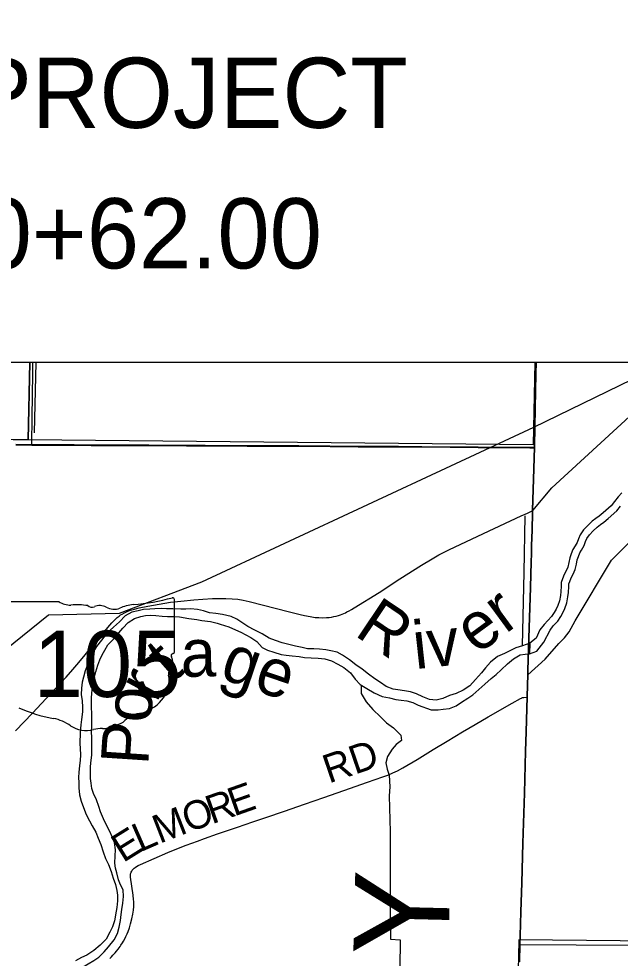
# Model space of a CAD drawing. Extents: x 0 to 34, y 0 to 22.
# Drawn here: x 6.448 to 7.646, y 14.995 to 16.867 of the extents above; entities that cross this region are included whole.
import ezdxf

# ---------------------------------------------------------------- set-up
doc = ezdxf.new("R2010")
doc.units = 0
for name, color, linetype in [('GM_X_City_Street', 7, 'Continuous'), ('GM_X_County_Road', 7, 'Continuous'), ('GM_X_County_Text', 7, 'Continuous'), ('GM_X_Major_River', 7, 'Continuous'), ('GM_X_Major_River_Text', 7, 'Continuous'), ('GM_X_Minor_River', 7, 'Continuous'), ('GM_X_Rail_Line', 7, 'Continuous'), ('GM_X_Section', 7, 'Continuous'), ('GM_X_State_Location', 7, 'Continuous'), ('GM_X_State_Route', 7, 'Continuous'), ('GM_X_State_Shield', 7, 'Continuous'), ('GM_X_Township_Road', 7, 'Continuous'), ('GM_X_Township_Road_Text', 7, 'Continuous'), ('GM_X_US_Route', 7, 'Continuous'), ('SH_Cut_Line', 7, 'Continuous'), ('SH_Text', 7, 'Continuous')]:
    doc.layers.add(name, color=color, linetype=linetype)

msp = doc.modelspace()

# ---------------------------------------------------------------- linework, layer by layer
at = {"layer": 'GM_X_City_Street'}
msp.add_lwpolyline([(7.4233, 14.1), (8.4275, 14.1), (8.4534, 15.0216), (7.4447, 15.0317), (7.4446, 15.029)], close=True, dxfattribs=at)
at = {"layer": 'GM_X_County_Road'}
msp.add_line((6.4425, 16.0181), (6.4745, 16.0177), dxfattribs=at)
for points in [[(6.4745, 16.0177), (6.5089, 16.0173), (6.5587, 16.0172), (6.5929, 16.017), (6.6302, 16.0168), (6.655, 16.0168), (6.7079, 16.0166), (6.7825, 16.0161), (6.8198, 16.0159), (6.9037, 16.0156), (7.0063, 16.0153), (7.0684, 16.0148), (7.1244, 16.0144), (7.2052, 16.0141), (7.2518, 16.0138), (7.3637, 16.0128), (7.4321, 16.0125), (7.4663, 16.0124), (7.4758, 16.0124)], [(7.4626, 15.5598), (7.4969, 15.5909), (7.5242, 15.6224), (7.5356, 15.6338), (7.5451, 15.6456), (7.5565, 15.6672), (7.6294, 15.7881), (7.7715, 15.9302)], [(7.447, 15.0225), (8.4514, 15.0162), (8.9, 15.0119)]]:
    msp.add_lwpolyline(points, dxfattribs=at)
at = {"layer": 'GM_X_Major_River'}
msp.add_line((7.4666, 15.6231), (7.4658, 15.6015), dxfattribs=at)
for points in [[(7.6498, 15.9222), (7.6426, 15.9146), (7.6354, 15.9051), (7.6282, 15.8963)], [(7.6282, 15.8963), (7.6123, 15.8829), (7.6044, 15.8761), (7.598, 15.8711), (7.5908, 15.8657), (7.5821, 15.8573), (7.5734, 15.8486), (7.567, 15.839), (7.5632, 15.831), (7.561, 15.8234), (7.5568, 15.8166), (7.5523, 15.8097), (7.5489, 15.8006), (7.5463, 15.793), (7.5444, 15.7839), (7.5422, 15.7744), (7.5388, 15.7668), (7.535, 15.7595), (7.5316, 15.7512), (7.529, 15.7439), (7.529, 15.7363), (7.5283, 15.7257), (7.5272, 15.7177), (7.5254, 15.7071), (7.5224, 15.698), (7.5186, 15.6907), (7.5148, 15.6839), (7.5099, 15.6763), (7.502, 15.6679), (7.4948, 15.6599), (7.4866, 15.6492), (7.4789, 15.6329), (7.4666, 15.6231)], [(7.64, 15.8867), (7.6473, 15.8957)], [(7.4658, 15.6015), (7.4802, 15.6069), (7.4942, 15.6249), (7.5067, 15.6485), (7.5131, 15.6576), (7.5219, 15.6669), (7.5279, 15.6761), (7.532, 15.6836), (7.5364, 15.6921), (7.5401, 15.7034), (7.5422, 15.7154), (7.5434, 15.7241), (7.5442, 15.7359), (7.5442, 15.7413), (7.5458, 15.7457), (7.5488, 15.7532), (7.5525, 15.7602), (7.5566, 15.7695), (7.5592, 15.7806), (7.5609, 15.789), (7.5632, 15.7955), (7.5659, 15.8028), (7.5696, 15.8085), (7.575, 15.8173), (7.5774, 15.8256), (7.5802, 15.8315), (7.5852, 15.8389), (7.5927, 15.8465), (7.6006, 15.8541), (7.6071, 15.859), (7.614, 15.8643), (7.6222, 15.8714), (7.64, 15.8867)], [(7.4666, 15.6231), (7.4517, 15.6179), (7.4383, 15.6133), (7.4264, 15.6079), (7.4161, 15.602), (7.4019, 15.5963), (7.3878, 15.5849), (7.3782, 15.5737), (7.3704, 15.5637), (7.3584, 15.5507), (7.3471, 15.5377), (7.3336, 15.5293), (7.3194, 15.5228), (7.3064, 15.5186), (7.2934, 15.5128), (7.2797, 15.509), (7.2669, 15.5108), (7.2534, 15.5157), (7.241, 15.5217), (7.2286, 15.5258), (7.2165, 15.5279), (7.2037, 15.5298), (7.1939, 15.5312), (7.18, 15.5368), (7.1689, 15.5447), (7.1577, 15.5521), (7.145, 15.5608), (7.1324, 15.5714), (7.1198, 15.58), (7.1071, 15.5894), (7.0933, 15.5989), (7.0829, 15.6048), (7.0701, 15.6078), (7.0599, 15.6095), (7.0478, 15.6106), (7.0365, 15.6113), (7.0236, 15.6116), (7.013, 15.6141), (6.9995, 15.6167), (6.9863, 15.6201), (6.9731, 15.6238), (6.96, 15.6283), (6.9472, 15.6328), (6.9331, 15.6415), (6.9189, 15.6486), (6.9046, 15.6562), (6.895, 15.6625), (6.8827, 15.6708), (6.8714, 15.676), (6.8545, 15.6798), (6.8409, 15.6817), (6.8284, 15.6831), (6.8164, 15.6872), (6.8046, 15.6901), (6.7908, 15.6912), (6.7809, 15.6907), (6.7711, 15.6906), (6.7556, 15.6913), (6.7427, 15.6912), (6.7325, 15.6919), (6.7196, 15.6914), (6.7097, 15.6909), (6.6968, 15.6897), (6.6865, 15.6873), (6.6736, 15.6846), (6.6605, 15.6773), (6.6489, 15.6654), (6.6369, 15.6547), (6.6248, 15.6432), (6.6135, 15.6291), (6.603, 15.6161), (6.5951, 15.603), (6.5895, 15.591), (6.5862, 15.5812), (6.5809, 15.568), (6.5772, 15.5552), (6.5747, 15.5454), (6.5733, 15.5329), (6.5729, 15.5204), (6.5749, 15.5082), (6.5757, 15.4957), (6.5751, 15.4858), (6.5736, 15.4707), (6.5722, 15.4601), (6.5707, 15.4449), (6.5701, 15.4229), (6.5707, 15.4127), (6.5715, 15.4001), (6.5708, 15.3891), (6.5694, 15.3789), (6.568, 15.3653), (6.5677, 15.3558), (6.5678, 15.3444), (6.568, 15.3349), (6.5695, 15.3209), (6.5726, 15.3079), (6.5772, 15.2953), (6.5826, 15.2818), (6.5894, 15.2688), (6.5949, 15.2592), (6.6017, 15.2461)], [(6.6554, 15.1051), (6.6573, 15.1184), (6.6561, 15.1313), (6.6514, 15.1416), (6.6471, 15.1512), (6.6437, 15.165), (6.6413, 15.1749), (6.6396, 15.1848), (6.6403, 15.1992), (6.641, 15.2114), (6.6391, 15.2254), (6.6348, 15.2369), (6.6298, 15.2477), (6.6229, 15.26), (6.6175, 15.2726), (6.6111, 15.2868), (6.6076, 15.2972), (6.603, 15.3106), (6.5976, 15.3232), (6.5941, 15.3336), (6.5924, 15.3438), (6.5915, 15.3534), (6.5915, 15.367), (6.5914, 15.3773), (6.5928, 15.3898), (6.5938, 15.3996), (6.5941, 15.4114), (6.594, 15.4224), (6.5943, 15.4341), (6.5935, 15.447), (6.5937, 15.4565), (6.594, 15.4694), (6.594, 15.4819), (6.5935, 15.4956), (6.5933, 15.5146), (6.5944, 15.5301), (6.5962, 15.5411), (6.5984, 15.5524), (6.6017, 15.566), (6.6058, 15.5788), (6.6099, 15.5897), (6.6143, 15.5995), (6.6198, 15.6092), (6.6261, 15.6193), (6.6374, 15.6308), (6.6479, 15.6432), (6.6559, 15.653), (6.6663, 15.6643), (6.679, 15.6719), (6.6915, 15.6758), (6.7011, 15.6778), (6.7105, 15.6784), (6.7216, 15.6777), (6.7344, 15.6766), (6.7449, 15.676), (6.7574, 15.6757), (6.7684, 15.6751), (6.7873, 15.6723), (6.8031, 15.67), (6.8133, 15.6683), (6.8303, 15.666), (6.8438, 15.663), (6.8499, 15.6608), (6.8668, 15.6552), (6.8799, 15.6496), (6.8907, 15.6448), (6.9008, 15.6392), (6.9109, 15.634), (6.9225, 15.6262), (6.9335, 15.6141), (6.9436, 15.609), (6.9568, 15.6048), (6.9714, 15.6003), (6.9812, 15.5989), (6.9933, 15.5975), (7.0073, 15.596), (7.0175, 15.5946), (7.0311, 15.5935), (7.0447, 15.5928), (7.0579, 15.5918), (7.0715, 15.588), (7.0842, 15.5813), (7.0961, 15.5745), (7.1091, 15.564), (7.1187, 15.5512), (7.1284, 15.5408), (7.142, 15.5324), (7.1566, 15.5237), (7.172, 15.5169), (7.187, 15.5139), (7.1995, 15.5109), (7.2104, 15.5091), (7.2214, 15.5081), (7.2334, 15.5048), (7.2442, 15.4996), (7.2701, 15.4902), (7.2838, 15.4899), (7.2937, 15.4915), (7.3062, 15.4924), (7.3199, 15.4978), (7.33, 15.5051)], [(7.33, 15.5051), (7.343, 15.5135), (7.3527, 15.5197), (7.3647, 15.5304), (7.3771, 15.5415), (7.3891, 15.5526), (7.3995, 15.5603), (7.4096, 15.5699), (7.422, 15.5814), (7.434, 15.5917), (7.447, 15.5994), (7.4569, 15.6011), (7.4658, 15.6015)], [(6.6017, 15.2461), (6.6068, 15.2346), (6.6121, 15.2215), (6.6167, 15.207), (6.6213, 15.1936), (6.6274, 15.1817), (6.6324, 15.1679), (6.6366, 15.1549), (6.6408, 15.1423), (6.6439, 15.1304), (6.6452, 15.1205), (6.6449, 15.1092), (6.6436, 15.0963), (6.6423, 15.0887), (6.6394, 15.0695), (6.6353, 15.0574), (6.6301, 15.0469), (6.6226, 15.0334), (6.6109, 15.0212), (6.5982, 15.0105), (6.5843, 15.0013), (6.5736, 14.9967), (6.5613, 14.9901)], [(6.4399, 14.9498), (6.4535, 14.9487), (6.4637, 14.9489), (6.4755, 14.9489), (6.4895, 14.9501), (6.5025, 14.9536), (6.515, 14.956), (6.5247, 14.9588), (6.5379, 14.9619), (6.5509, 14.9676), (6.5612, 14.9712), (6.5734, 14.9758), (6.5865, 14.9838), (6.5977, 14.9904), (6.6077, 14.997), (6.6185, 15.0077), (6.6275, 15.0181), (6.6385, 15.0319), (6.6448, 15.0447), (6.6482, 15.0567), (6.6508, 15.0703), (6.6522, 15.082), (6.654, 15.0922), (6.6554, 15.1051)]]:
    msp.add_lwpolyline(points, dxfattribs=at)
at = {"layer": 'GM_X_Minor_River'}
msp.add_line((6.4826, 16.1819), (6.4791, 16.0422), dxfattribs=at)
for points in [[(7.4521, 15.6183), (7.4553, 15.7635), (7.457, 15.8766)], [(7.1308, 15.5369), (7.1308, 15.5224), (7.1403, 15.5059), (7.1539, 15.4904), (7.1691, 15.4763), (7.1809, 15.4639), (7.195, 15.4541), (7.2098, 15.4397), (7.2107, 15.429), (7.2003, 15.4213), (7.1921, 15.412), (7.183, 15.3974), (7.1797, 15.3846), (7.182, 15.3717), (7.1862, 15.3602), (7.1879, 15.3366), (7.186, 15.3188), (7.1884, 15.2467), (7.1884, 15.1104), (7.1887, 15.033), (7.2084, 15.0321), (7.2067, 14.9179)]]:
    msp.add_lwpolyline(points, dxfattribs=at)
at = {"layer": 'GM_X_Rail_Line'}
for points in [[(7.4742, 16.0534), (7.8661, 16.2441), (7.8862, 16.2455), (8.0808, 16.409), (8.1603, 16.4709), (8.5168, 16.8244), (8.6624, 16.9647), (8.9, 17.2081)], [(5.4683, 15.0207), (5.6332, 15.1067), (5.7819, 15.1753), (6.2027, 15.4338), (6.5076, 15.6796), (6.6489, 15.6828), (6.8134, 15.745), (7.4742, 16.0534)]]:
    msp.add_lwpolyline(points, dxfattribs=at)
at = {"layer": 'GM_X_Section'}
for points in [[(6.4705, 16.1819), (6.4673, 16.0279), (6.437, 16.0283), (5.476, 16.0344), (5.4985, 17.0434), (6.488, 17.04), (6.4858, 16.9319)], [(7.4762, 16.1819), (7.4734, 16.0179), (6.4673, 16.0279), (6.4705, 16.1819)]]:
    msp.add_lwpolyline(points, dxfattribs=at)
at = {"layer": 'GM_X_State_Route'}
for points in [[(7.4722, 15.887), (7.5101, 15.9321), (7.7055, 16.1117), (7.8205, 16.2154), (8.0065, 16.3511), (8.0705, 16.3981), (8.1716, 16.4806), (8.2905, 16.5979), (8.4388, 16.7459), (8.5901, 16.8939), (8.6621, 16.9631), (8.9, 17.2081)], [(6.4419, 15.4479), (6.4756, 15.4837), (6.5212, 15.5321), (6.5426, 15.5554), (6.5559, 15.5701), (6.568, 15.5842), (6.5808, 15.5995), (6.5889, 15.6097), (6.596, 15.6184), (6.6131, 15.639), (6.6256, 15.6543), (6.6339, 15.6635), (6.64, 15.6697), (6.6445, 15.6738), (6.6481, 15.6767), (6.6514, 15.6791), (6.6545, 15.6809), (6.6593, 15.6836), (6.6644, 15.6859), (6.6713, 15.6885), (6.679, 15.6908), (6.688, 15.693), (6.7056, 15.6967), (6.7282, 15.7009), (6.7509, 15.7043), (6.7713, 15.7068), (6.7972, 15.7094), (6.8152, 15.7108), (6.8344, 15.7117), (6.8493, 15.7122), (6.8611, 15.7121), (6.8734, 15.7115), (6.8845, 15.7103), (6.8955, 15.7084), (6.9076, 15.7058), (6.9877, 15.6853), (7.0088, 15.6799), (7.0179, 15.6778), (7.0289, 15.6757), (7.0388, 15.6743), (7.0463, 15.6737), (7.0538, 15.6734), (7.0614, 15.6737), (7.0665, 15.674), (7.0717, 15.6748), (7.0763, 15.6757), (7.0809, 15.6767), (7.085, 15.6779), (7.0891, 15.6793), (7.0929, 15.6808), (7.0962, 15.6822), (7.099, 15.6836), (7.1022, 15.6852), (7.1067, 15.6875), (7.1109, 15.6899), (7.1166, 15.6932), (7.1662, 15.7241), (7.2076, 15.751), (7.2508, 15.7782), (7.2721, 15.7911), (7.2855, 15.7988), (7.2946, 15.8036), (7.305, 15.8086), (7.374, 15.8413), (7.449, 15.8763), (7.4617, 15.8822), (7.4722, 15.887)]]:
    msp.add_lwpolyline(points, dxfattribs=at)
at = {"layer": 'GM_X_State_Shield'}
for p, q in [((6.5286, 15.7052), (6.4321, 15.7052)), ((6.7585, 15.6054), (6.7585, 15.7101)), ((6.7584, 15.6055), (6.7585, 15.6054))]:
    msp.add_line(p, q, dxfattribs=at)
for centre, major_axis, start_param, end_param in [((6.5516, 15.7284), (0.037, 0), 4.042523, 4.731795), ((6.6411, 15.978), (0.3495, 0), 4.814394, 5.042369), ((6.7548, 15.7106), (0.00367, 0), 6.141152, 7.989035), ((6.5639, 15.5928), (0.133, 0), 1.404758, 1.657858), ((6.5941, 15.7032), (0.0107, 0), 3.836095, 5.185415), ((6.6098, 15.6801), (0.0222, 0), 0.950623, 2.079405), ((6.6384, 15.7118), (0.0267, 0), 4.081561, 5.145723), ((6.6856, 15.644), (0.0703, 0), 1.699011, 2.107814), ((6.7576, 15.5978), (0.00568, 0), 1.883978, 3.671073), ((6.7215, 15.5845), (0.0341, 0), 5.934695, 6.695948), ((6.7545, 15.605), (0.00393, 0), 5.05454, 6.418171), ((6.7716, 15.5616), (0.0248, 0), 2.387724, 3.262537), ((6.6606, 15.5483), (0.0874, 0), 5.101752, 6.440018), ((6.5731, 15.6699), (0.2524, 0), 4.195997, 4.488961), ((6.6975, 15.4454), (0.0479, 0), 1.647645, 2.488434), ((6.4979, 15.4117), (0.079, 0), 0.823519, 1.323587), ((6.64, 15.4547), (0.00752, 0), 1.147584, 2.315152), ((6.6368, 15.4822), (0.0282, 0), 4.937069, 5.64225), ((6.5833, 15.4891), (0.0501, 0), 4.026481, 4.996735), ((6.6122, 15.4199), (0.0412, 0), 1.495662, 1.94098), ((6.6159, 15.4741), (0.0267, 0), 4.691044, 5.507374)]:
    msp.add_ellipse(centre, major_axis=major_axis, ratio=0.8, start_param=start_param, end_param=end_param, dxfattribs=at)
at = {"layer": 'GM_X_Township_Road'}
msp.add_line((6.4425, 16.0181), (6.4745, 16.0177), dxfattribs=at)
for points in [[(6.4745, 16.0177), (6.4746, 16.0247), (6.4749, 16.0682), (6.4758, 16.1211), (6.4763, 16.1553), (6.4767, 16.1819)], [(6.6295, 14.9946), (6.6331, 14.998), (6.6361, 15.0011), (6.6378, 15.0029), (6.6407, 15.0061), (6.6434, 15.0092), (6.6463, 15.0129), (6.6504, 15.0188), (6.6518, 15.0209), (6.6549, 15.0256), (6.6571, 15.0292), (6.6597, 15.0335), (6.6619, 15.0381), (6.6646, 15.0438), (6.6664, 15.0484), (6.6688, 15.0556), (6.6711, 15.0634), (6.6738, 15.0736), (6.6758, 15.0828), (6.677, 15.0909), (6.6775, 15.0984), (6.6777, 15.1017), (6.6777, 15.105), (6.6775, 15.1082), (6.6771, 15.1121), (6.6761, 15.1208), (6.671, 15.1565), (6.6708, 15.1586), (6.6709, 15.1611), (6.6712, 15.1632), (6.6716, 15.1649), (6.6723, 15.1668), (6.6734, 15.1689), (6.6745, 15.1706), (6.6761, 15.1728), (6.678, 15.1745), (6.6801, 15.1761), (6.683, 15.1778), (6.6862, 15.1796), (6.6907, 15.1817), (6.7453, 15.2059), (6.763, 15.2131), (6.7816, 15.2201), (6.8044, 15.2284), (6.8184, 15.2335), (6.8444, 15.2427), (6.8842, 15.2563), (6.9148, 15.2669), (6.9407, 15.2757), (6.9777, 15.2884), (7.0177, 15.3023), (7.0559, 15.3154), (7.0958, 15.3294), (7.1428, 15.3457), (7.1734, 15.3563), (7.1833, 15.36), (7.1937, 15.3644), (7.2027, 15.3687), (7.2136, 15.3745), (7.2421, 15.3912), (7.274, 15.4107), (7.3021, 15.4278), (7.3324, 15.4461), (7.3577, 15.4608), (7.3835, 15.4758), (7.4314, 15.5036), (7.448, 15.5129), (7.4496, 15.5136), (7.4507, 15.5141), (7.452, 15.5144), (7.4531, 15.5147), (7.4545, 15.5148), (7.4612, 15.5155)]]:
    msp.add_lwpolyline(points, dxfattribs=at)
at = {"layer": 'GM_X_US_Route'}
for points in [[(6.4423, 16.0187), (6.4743, 16.0183), (6.5087, 16.0179), (6.5585, 16.0178), (6.5926, 16.0175), (6.6299, 16.0174), (6.6548, 16.0173), (6.7076, 16.0171), (6.7822, 16.0166), (6.8195, 16.0164), (6.9035, 16.0161), (7.006, 16.0159), (7.0682, 16.0154), (7.1241, 16.0149), (7.205, 16.0146), (7.2516, 16.0143), (7.3635, 16.0133), (7.4318, 16.013), (7.4661, 16.013), (7.4756, 16.0129), (7.4756, 16.0152), (7.4772, 16.0914), (7.4787, 16.1597), (7.4792, 16.1819)], [(7.4792, 16.1819), (7.4787, 16.1597), (7.4772, 16.0914), (7.4756, 16.0152), (7.4756, 16.0129), (7.4739, 15.9499), (7.4719, 15.8876), (7.4716, 15.8785), (7.4701, 15.8272), (7.47, 15.8225), (7.4695, 15.8008), (7.4692, 15.7852), (7.4675, 15.734), (7.4652, 15.6532), (7.4627, 15.5693), (7.4624, 15.5603), (7.461, 15.5165), (7.461, 15.5161), (7.4591, 15.4465), (7.458, 15.4077), (7.4555, 15.3238), (7.4525, 15.2244), (7.4502, 15.1451), (7.4484, 15.0877), (7.4472, 15.0395), (7.4467, 15.0231), (7.4458, 14.9882)], [(7.4758, 16.0124), (7.4759, 16.0147), (7.4774, 16.0908), (7.479, 16.1592), (7.4794, 16.1819)], [(7.4458, 14.9882), (7.4467, 15.0231), (7.4472, 15.0395), (7.4484, 15.0877), (7.4502, 15.1451), (7.4525, 15.2244), (7.4555, 15.3238), (7.458, 15.4077), (7.4591, 15.4465), (7.461, 15.5161), (7.461, 15.5165), (7.4624, 15.5603), (7.4627, 15.5693), (7.4652, 15.6532), (7.4675, 15.734), (7.4692, 15.7852), (7.4695, 15.8008), (7.47, 15.8225), (7.4701, 15.8272), (7.4716, 15.8785), (7.4719, 15.8876), (7.4739, 15.9499), (7.4756, 16.0129), (7.4661, 16.013), (7.4318, 16.013), (7.3635, 16.0133), (7.2516, 16.0143), (7.205, 16.0146), (7.1241, 16.0149), (7.0682, 16.0154), (7.006, 16.0159), (6.9035, 16.0161), (6.8195, 16.0164), (6.7822, 16.0166), (6.7076, 16.0171), (6.6548, 16.0173), (6.6299, 16.0174), (6.5926, 16.0175), (6.5585, 16.0178), (6.5087, 16.0179), (6.4743, 16.0183), (6.4423, 16.0187)], [(7.4461, 14.9877), (7.447, 15.0225), (7.4474, 15.0389), (7.4486, 15.0871), (7.4504, 15.1446), (7.4527, 15.2238), (7.4557, 15.3232), (7.4583, 15.4071), (7.4593, 15.446), (7.4612, 15.5155), (7.4626, 15.5598), (7.4629, 15.5687), (7.4654, 15.6526), (7.4678, 15.7334), (7.4695, 15.7847), (7.4697, 15.8002), (7.4703, 15.822), (7.4703, 15.8267), (7.4719, 15.8779), (7.4722, 15.887), (7.4741, 15.9494), (7.4758, 16.0124)]]:
    msp.add_lwpolyline(points, dxfattribs=at)
at = {"layer": 'SH_Cut_Line'}
for points in [[(7.4458, 14.9882), (7.4467, 15.0231), (7.4472, 15.0395), (7.4484, 15.0877), (7.4502, 15.1451), (7.4525, 15.2244), (7.4555, 15.3238), (7.458, 15.4077), (7.4591, 15.4465), (7.461, 15.5161), (7.461, 15.5165), (7.4624, 15.5603), (7.4627, 15.5693), (7.4652, 15.6532), (7.4675, 15.734), (7.4692, 15.7852), (7.4695, 15.8008), (7.47, 15.8225), (7.4701, 15.8272), (7.4716, 15.8785), (7.4719, 15.8876), (7.4739, 15.9499), (7.4756, 16.0129), (7.4756, 16.0152), (7.4772, 16.0914), (7.4787, 16.1597), (7.4792, 16.1819)], [(7.4792, 16.1819), (7.4787, 16.1597), (7.4772, 16.0914), (7.4756, 16.0152), (7.4756, 16.0129), (7.4739, 15.9499), (7.4719, 15.8876), (7.4716, 15.8785), (7.4701, 15.8272), (7.47, 15.8225), (7.4695, 15.8008), (7.4692, 15.7852), (7.4675, 15.734), (7.4652, 15.6532), (7.4627, 15.5693), (7.4624, 15.5603), (7.461, 15.5165), (7.461, 15.5161), (7.4591, 15.4465), (7.458, 15.4077), (7.4555, 15.3238), (7.4525, 15.2244), (7.4502, 15.1451), (7.4484, 15.0877), (7.4472, 15.0395), (7.4467, 15.0231), (7.4458, 14.9882)]]:
    msp.add_lwpolyline(points, dxfattribs=at)
at = {"layer": 'SH_Text'}
msp.add_lwpolyline([(5.7647, 16.9319), (7.7647, 16.9319), (7.7647, 16.1819), (5.7647, 16.1819)], close=True, dxfattribs=at)

# ---------------------------------------------------------------- texts
at = {"layer": 'GM_X_County_Text'}
msp.add_text('Y', height=0.1894, rotation=88.6072, dxfattribs=at).set_placement((7.3041, 14.9987))
at = {"layer": 'GM_X_Major_River_Text'}
for s, height, rotation, p in [('er', 0.09475, 36.2255, (7.3608, 15.5987)), ('R', 0.0948, 326.2233, (7.1147, 15.6397)), ('iv', 0.09475, 6.2243, (7.2383, 15.571)), ('a', 0.0948, 1.2236, (6.7717, 15.5554)), ('t', 0.0948, 41.2253, (6.7544, 15.5423)), ('ge', 0.09475, 341.2231, (6.8462, 15.5532)), ('r', 0.0948, 61.2258, (6.7224, 15.5027)), ('Po', 0.09476, 86.2254, (6.7061, 15.3786))]:
    msp.add_text(s, height=height, rotation=rotation, dxfattribs=at).set_placement(p)
at = {"layer": 'GM_X_State_Location'}
msp.add_text('105', height=0.000189, rotation=0, dxfattribs=at).set_placement((6.5231, 15.5746))
for s in ['s', 'r']:
    msp.add_text(s, height=0.000189, dxfattribs=at).set_placement((6.59, 15.5884))
at = {"layer": 'GM_X_State_Shield'}
msp.add_text('105', height=0.13184, dxfattribs=at).set_placement((6.478, 15.5157))
at = {"layer": 'GM_X_Township_Road_Text'}
for s, height, rotation, p in [('RD', 0.05682, 18.8993, (7.0661, 15.343)), ('E', 0.0568, 19.4556, (6.877, 15.2773)), ('O', 0.0568, 19.4752, (6.7858, 15.2451)), ('R', 0.0568, 19.4039, (6.833, 15.2618)), ('M', 0.0568, 21.2793, (6.7288, 15.2229)), ('E', 0.0568, 31.8641, (6.6563, 15.1846)), ('L', 0.0568, 23.6488, (6.6905, 15.2061))]:
    msp.add_text(s, height=height, rotation=rotation, dxfattribs=at).set_placement(p)
at = {"layer": 'SH_Text'}
for s, p in [('END PROJECT', (5.9023, 16.6495)), ('STA. 0+62.00', (5.9023, 16.3695))]:
    msp.add_text(s, height=0.14, dxfattribs=at).set_placement(p)

doc.saveas('drawing.dxf')
